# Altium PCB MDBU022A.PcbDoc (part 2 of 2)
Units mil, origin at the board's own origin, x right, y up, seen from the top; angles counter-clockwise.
Board outline 3500 x 2200 mil, 2 copper layers (Top Layer, Bottom Layer), stack 64.8 mil thick; 115 components, 70 nets, 323 pads, 476 vias.
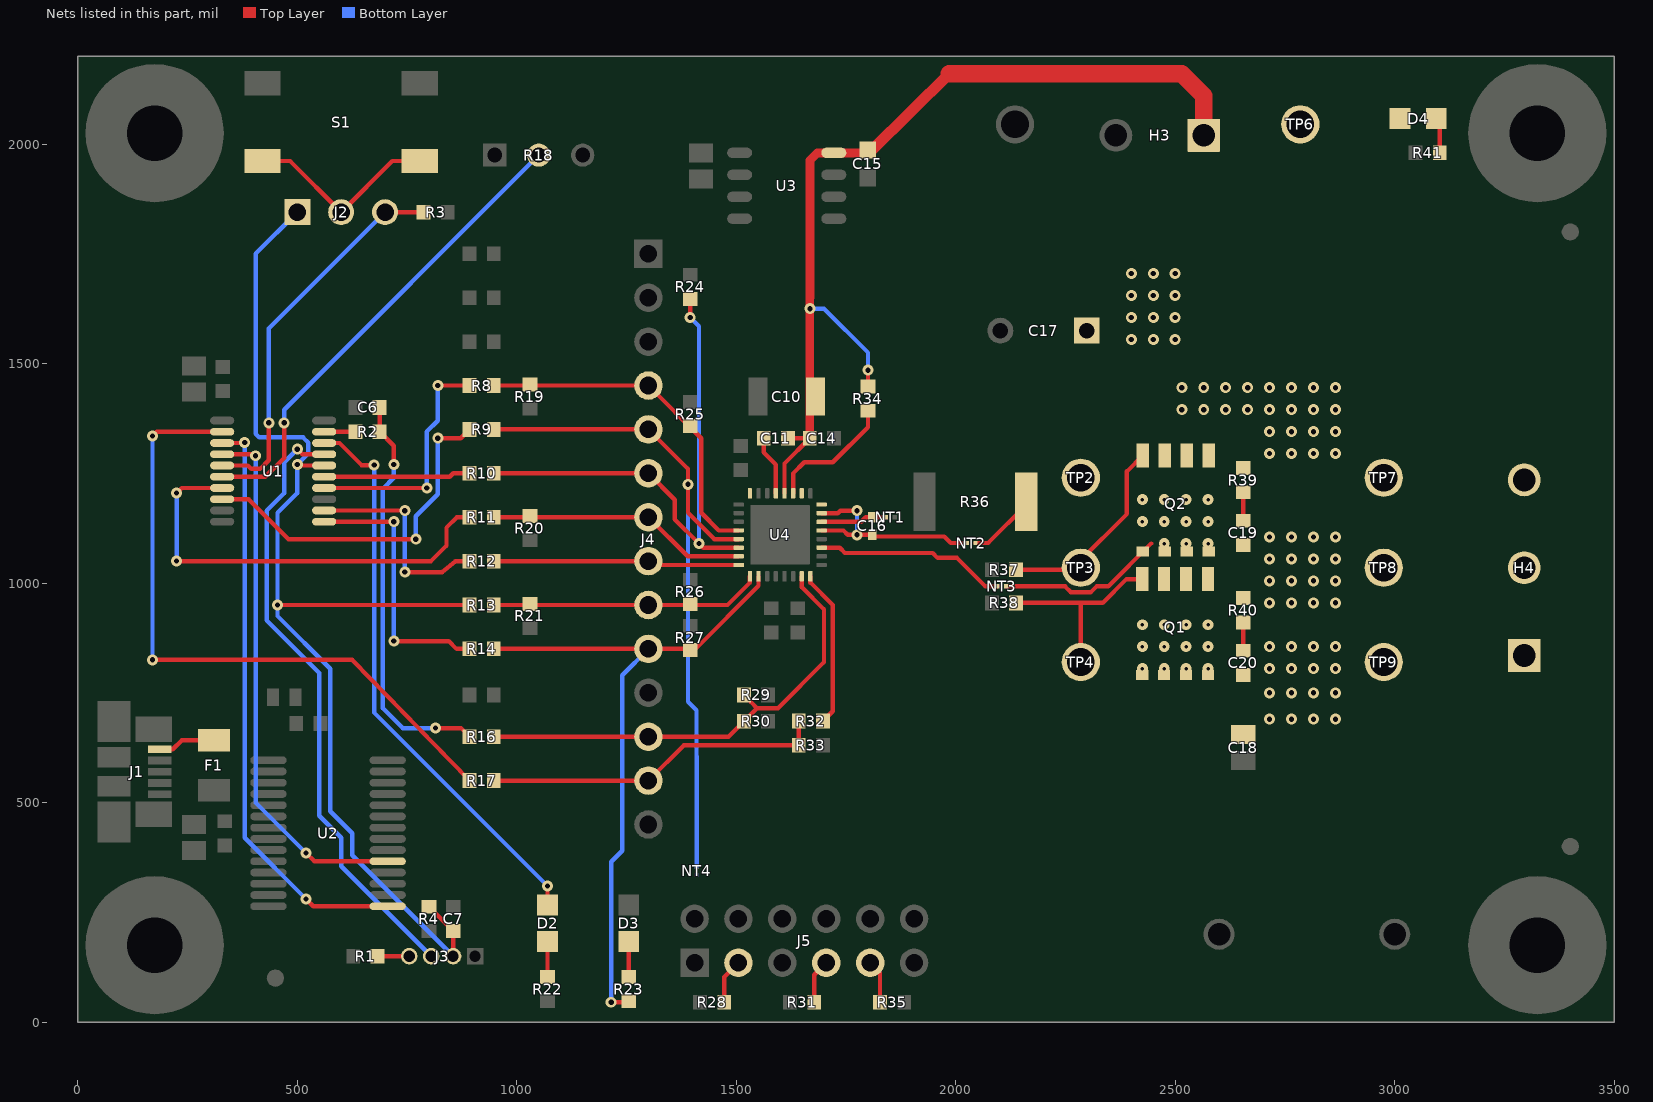
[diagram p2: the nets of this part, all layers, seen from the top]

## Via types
v1: diameter 25, hole 12, Top Layer to Bottom Layer, tented both sides, 446 vias
v2: diameter 25, hole 7.82, Top Layer to Bottom Layer, tented both sides, 23 vias
v3: diameter 19.68, hole 7.87, Top Layer to Bottom Layer, 5 vias
v4: diameter 25, hole 12, Top Layer to Bottom Layer, 2 vias

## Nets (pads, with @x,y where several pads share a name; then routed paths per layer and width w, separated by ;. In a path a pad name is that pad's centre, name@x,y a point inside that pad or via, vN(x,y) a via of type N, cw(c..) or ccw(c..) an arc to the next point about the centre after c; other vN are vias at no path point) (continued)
NetC19_2: C19.2 R39.2 | length 64.9
  Top Layer w10: C19.2@2655,1142.01 R39.2@2655,1206.89
NetC20_2: C20.2 R40.2 | length 64.9
  Top Layer w10: C20.2@2655,845.61 R40.2@2655,910.49
NetD2_2: D2.2 R22.2 | length 81.1
  Top Layer w10: R22.2@1070,102.56 D2.2@1070,183.66
NetD3_2: D3.2 R23.2 | length 81.1
  Top Layer w10: R23.2@1255,102.56 D3.2@1255,183.66
NetD4_2: D4.2 R41.2 | length 76.6
  Top Layer w10: D4.2@3090.75,2054.49 D4.2@3094.53,2058.27 ; R41.2@3103.05,1980 D4.2@3103.05,2051.22
NetF1_2: F1.2 J1.1 | length 138.7
  Top Layer w10: J1.1@180,621.18 216.18,621.18 237.09,642.09 F1.2@310,642.09
NetH4_3: H4.3 NT2.1 Q2.1 Q2.2 Q2.3 R36.2 R39.1 TP2.1 TP7.1 | length 152.3
  Top Layer w10: NT2.1@2045,1091.25 2073.75,1091.25 R36.2@2161.14,1178.64
  other v1: 2715,1295 2765,1295 2815,1295 2865,1295 2715,1345 2765,1345 2815,1345 2865,1345 2515,1395 2565,1395 2615,1395 2665,1395 2715,1395 2765,1395 2815,1395 2865,1395 2515,1445 2565,1445 2615,1445 2665,1445 2715,1445 2765,1445 2815,1445 2865,1445
NetJ2_2: J2.2 S1.1 S1.2 | length 454.7
  Top Layer w10: S1.2@420.87,1961.42 483.58,1961.42 J2.2@600,1845 716.42,1961.42 S1.1@779.13,1961.42
NetJ3_4: J3.4 R1.1 | length 72.4
  Top Layer w10: R1.1@682.56,150 J3.4@755,150
NetJ5_3: J5.3 R28.1 | length 103.4
  Top Layer w10: R28.1@1472.56,45 1472.56,102.56 J5.3@1505,135
NetJ5_7: J5.7 R31.2 | length 101.4
  Top Layer w10: R31.2@1677.56,45 1677.56,107.56 J5.7@1705,135
NetJ5_9: J5.9 R35.2 | length 99.3
  Top Layer w10: J5.9@1805,135 1827.44,112.56 R35.2@1827.44,45
NetQ1_4: Q1.4 R38.2 TP4.1 | length 444.3
  Top Layer w10: R38.2@2137.56,954.7 2260.3,954.7 2334.7,954.7 2389.1,1009.1 Q1.4@2424.65,1009.1 ; TP4.1@2285,820 2285,954.7
NetQ2_4: Q2.4 R37.2 TP3.1 | length 453.3
  Top Layer w10: R37.2@2137.56,1030 2262.55,1030 2282.55,1050 2390,1157.45 2390,1254.35 Q2.4@2426.18,1290.53
NetR2_1: R2.1 U1.19 | length 70.9
  Top Layer w10: U1.19@561.14,1344.57 R2.1@632.01,1344.57
NetR32_1: R32.1 U4.16 | length 360.3
  Top Layer w10: U4.16@1668.9,1015.51 1668.9,1001.1 1720,950 1720,708.11 R32.1@1697.56,685.67
NetU4_24: U4.24
NetU4_26: U4.26
NetU4_32: U4.32
NFAULT: J4.10 R14.1 R23.1 R27.2 U4.10 | length 1565.7
  Top Layer w10: R14.1@947.56,850 J4.10@1300,850 1407,850 1550.79,993.79 U4.10@1550.79,1015.51 ; v1(1215,45) 1252.56,45 R23.1@1255,47.44
  Bottom Layer w10: v1(1215,45) 1215,365 1240,390 1240,790 J4.10@1300,850
NFAULT_MCU: R14.2 U1.11 | length 610.7
  Top Layer w10: U1.11@561.14,1139.84 v1(720,1139.84) ; v1(720,867.82) 845,867.82 862.82,850 R14.2@892.44,850
  Bottom Layer w10: v1(720,867.82) v1(720,1139.84)
NSCS: J4.5 NT4.1 R9.1 U4.5 | length 1597.8
  Top Layer w10: R9.1@948.05,1350 J4.5@1300,1350 1390,1260 v1(1390,1225) 1390,1160 1449.84,1100.16 U4.5@1505.51,1100.16
  Bottom Layer w10: v1(1390,1225) 1390,729.65 1409.5,710.15 1409.5,605.5 1410,605 NT4.1@1410,355
NSCS_MCU: R9.2 U1.8 | length 810.3
  Top Layer w10: U1.8@328.86,1191.02 388.98,1191.02 480,1100 v1(770,1100) ; v1(820,1330) 872.44,1330 R9.2@892.44,1350
  Bottom Layer w10: v1(770,1100) 770,1152.11 820,1202.11 v1(820,1330)
NSLEEP: J4.8 R12.1 U4.8 | length 561.6
  Top Layer w10: R12.1@947.56,1050 J4.8@1300,1050 1308.9,1041.1 U4.8@1505.51,1041.1
NSLEEP_MCU: R12.2 U1.12 | length 480.4
  Top Layer w10: U1.12@561.14,1165.43 v1(745,1165) ; v1(745,1025) 830,1025 860,1050 R12.2@892.44,1050
  Bottom Layer w10: v1(745,1025) v1(745,1165)
OUT1: C19.1 H4.2 NT3.2 Q1.1 Q1.2 Q1.3 Q2.5 Q2.6 Q2.7 Q2.8 R40.1 TP8.1 | length 381.1
  Top Layer w10: NT3.2@2115,992.35 2249.16,992.35 2262.01,979.5 2307.99,979.5 2320.84,992.35 2347.35,992.35 2445,1090
  other v1: 2715,955 2765,955 2815,955 2865,955 2715,1005 2765,1005 2815,1005 2865,1005 2715,1055 2765,1055 2815,1055 2865,1055 2715,1105 2765,1105 2815,1105 2865,1105
  other v2: 2475,1090 2525,1090 2575,1090 2425,1140 2475,1140 2525,1140 2575,1140 2425,1190 2475,1190 2525,1190 2575,1190
POT: R18.2 U1.6 | length 1089.1
  Top Layer w10: U1.6@328.86,1242.2 427.2,1242.2 470,1285 v1(470,1365)
  Bottom Layer w10: v1(470,1365) 470,1395 R18.2@1050,1975
PUSH: J2.3 R3.1 U1.5 | length 879.9
  Top Layer w10: U1.5@328.86,1267.8 387.2,1267.8 395,1260 415,1260 435,1280 v1(435,1365) ; J2.3@700,1845 R3.1@787.44,1845
  Bottom Layer w10: v1(435,1365) 435,1580 J2.3@700,1845
PVDD: C10.1 C11.2 C14.1 C15.1 C17.1 C18.1 C20.1 D4.1 H3.1 H4.1 Q1.5 Q1.6 Q1.7 Q1.8 R34.1 TP6.1 TP9.1 U3.8 U4.28 | length 2159.1
  Top Layer w10: U4.28@1609.84,1204.49 1609.84,1272.4 C14.1@1667.44,1330 C11.2@1617.56,1330 ; C15.1@1797.44,1980 C15.1@1800,1982.56 ; R34.1@1800,1447.56 v1(1800,1485)
  Top Layer w20: C14.1@1667.44,1330 1668.15,1963.15 1685,1980 U3.8@1722.28,1980 C15.1@1797.44,1980
  Top Layer w25: C15.1@1810,1988.05 1985,2160
  Top Layer w40: 1985,2160 2515,2160 2565,2110 H3.1@2565,2020
  Bottom Layer w10: v1(1668.15,1625) 1700,1625 1800,1525 v1(1800,1485)
  other v1: 2715,690 2765,690 2815,690 2865,690 2715,750 2765,750 2815,750 2865,750 2715,805 2765,805 2815,805 2865,805 2715,855 2765,855 2815,855 2865,855 2400,1555 2450,1555 2500,1555 2400,1605 2450,1605 2500,1605 2400,1655 2450,1655 2500,1655 2400,1705 2450,1705 2500,1705
  other v2: 2425,805 2475,805 2525,805 2575,805 2425,855 2475,855 2525,855 2575,855 2425,905 2475,905 2525,905 2575,905
RESET: C7.1 J2.1 J3.2 R4.1 R13.2 U1.16 | length 2671.7
  Top Layer w10: v1(455,950) R13.2@891.95,950 ; v1(500,1270) 502.2,1267.8 U1.16@561.14,1267.8 ; R4.1@800,262.56 800,262.44 C7.1@855,207.44 J3.2@855,150
  Bottom Layer w10: J2.1@500,1845 405,1750 405,1340 413.13,1331.87 513.13,1331.87 525,1320 525,1295 v1(500,1270) 500,1205 455,1160 v1(455,950) 455,925 575,805 575,480 625,430 625,380 J3.2@855,150
RX: U1.4 U2.5 | length 1223.9
  Top Layer w10: U1.4@328.86,1293.39 401.61,1293.39 v1(405,1290) ; v1(520,385) 538.98,366.02 U2.5@705.83,366.02
  Bottom Layer w10: v1(405,1290) 405,500 v1(520,385)
S_N: C16.2 NT1.1 U4.22 | length 150.2
  Top Layer w10: U4.22@1694.49,1139.53 1784.84,1139.53 1795,1149.69 C16.2@1810,1149.69 ; C16.2@1810.31,1150 NT1.1@1840.76,1150
S_P: C16.1 NT2.2 U4.21 U4.23 | length 492.6
  Top Layer w10: U4.21@1694.49,1119.84 1744.2,1119.84 1754.04,1110 v4(1775,1110) ; U4.23@1694.49,1159.21 1731.48,1159.21 1737.26,1165 v4(1775,1165) ; v4@1765.32,1110.32 C16.1@1810,1110.32 1810,1106.07 1973.93,1106.07 1988.75,1091.25 NT2.2@2025,1091.25
  Bottom Layer w10: v4(1775,1110) v4(1775,1165)
SCLK: J4.7 R11.1 R20.2 U4.7 | length 594.9
  Top Layer w10: R11.1@947.56,1150 J4.7@1300,1150 1389.21,1060.79 U4.7@1505.51,1060.79
SCLK_MCU: R11.2 U1.7 | length 996.6
  Top Layer w10: v1(225,1050) 804.65,1050 840,1085.35 840,1126.4 863.6,1150 R11.2@892.44,1150 ; v1(225,1205) 236.61,1216.61 U1.7@328.86,1216.61
  Bottom Layer w10: v1(225,1050) v1(225,1205)
SDI: J4.6 R10.1 R24.2 U4.6 | length 1215.3
  Top Layer w10: R10.1@947.56,1250 J4.6@1300,1250 1360,1190 1360,1145 v1(1415,1090) 1424.53,1080.47 U4.6@1505.51,1080.47 ; v1(1395,1605) R24.2@1395,1642.44
  Bottom Layer w10: v1(1395,1605) 1415,1585 v1(1415,1090)
SDI_MCU: R10.2 U1.15 | length 334
  Top Layer w10: U1.15@561.14,1242.2 847.2,1242.2 855,1250 R10.2@891.95,1250
SDO: J4.4 R8.1 R19.2 R25.1 U4.4 | length 794.3
  Top Layer w10: R8.1@947.56,1450 J4.4@1300,1450 1420,1330 1420,1160 1460.16,1119.84 U4.4@1505.51,1119.84
SDO_MCU: R8.2 U1.14 | length 549.5
  Top Layer w10: U1.14@561.14,1216.61 v1(795,1216.61) ; v1(820,1450) R8.2@891.95,1450
  Bottom Layer w10: v1(795,1216.61) 795,1345 820,1370 v1(820,1450)
SH: NT3.1 U4.19 | length 437
  Top Layer w10: U4.19@1694.49,1080.47 1735.49,1080.47 1747.46,1068.5 1947.46,1068.5 1958.71,1057.25 2002.75,1057.25 2067.65,992.35 NT3.1@2095,992.35
SO: J4.13 R17.1 R32.2 R33.2 | length 783.3
  Top Layer w10: R17.1@947.56,550 J4.13@1300,550 1380.67,630.67 R33.2@1642.44,630.67 ; R33.2@1642.44,633.46 R32.2@1642.44,688.46
SO_MCU: R17.2 U1.2 | length 1511.4
  Top Layer w10: v1(170,825) 625,825 R17.2@892.44,550 ; v1(170,1335) 179.57,1344.57 U1.2@328.86,1344.57
  Bottom Layer w10: v1(170,825) v1(170,1335)
STATUS: D2.1 U1.18 | length 1300.7
  Top Layer w10: U1.18@561.14,1318.98 596.02,1318.98 645,1270 646.27,1268.73 v1(675,1268.73) ; D2.1@1070,266.34 v1(1070,310)
  Bottom Layer w10: v1(675,1268.73) 675,1235 675,705 v1(1070,310)
TEST: J3.3 U1.17 | length 1405.3
  Top Layer w10: v1(500,1305) 511.61,1293.39 U1.17@561.14,1293.39
  Bottom Layer w10: v1(500,1305) 470,1275 470,1205 430,1165 430,915 550,795 550,470 600,420 600,355 J3.3@805,150
TX: U1.3 U2.1 | length 1342.1
  Top Layer w10: U1.3@328.86,1318.98 378.98,1318.98 v1(380,1320) ; v1(520,280) 536.34,263.66 U2.1@705.83,263.66
  Bottom Layer w10: v1(380,1320) 380,420 v1(520,280)
VCP: C11.1 U4.29 | length 137
  Top Layer w10: C11.1@1562.44,1330 1562.44,1297.56 1590.16,1269.84 U4.29@1590.16,1204.49
VDRAIN: R34.2 U4.27 | length 296.1
  Top Layer w10: U4.27@1629.53,1204.49 1629.53,1249.53 1655,1275 1720,1275 1800,1355 R34.2@1800,1391.95
VREF: J4.12 R16.1 R29.2 R30.1 U4.15 | length 1081.8
  Top Layer w10: R16.1@947.56,650 J4.12@1300,650 1482.44,650 R30.1@1517.44,685 1547.44,715 ; R29.2@1517.44,745 1532.44,730 1547.44,715 ; U4.15@1649.21,1015.51 1649.21,990.79 1700,940 1700,820 1595,715 1547.44,715
VREF_MCU: C6.1 R2.2 R16.2 | length 933.1
  Top Layer w10: C6.1@687.56,1400 R2.2@687.56,1345 719.89,1312.67 v1(719.89,1270) ; v1(815,669.61) 872.83,669.61 R16.2@892.44,650
  Bottom Layer w10: v1(719.89,1270) 719.89,1239.89 695,1215 695,715 740.39,669.61 v1(815,669.61)
WDFLT: J4.9 R13.1 R21.2 R26.2 U4.9 | length 619.1
  Top Layer w10: R13.1@947.56,950 J4.9@1300,950 1480,950 1531.1,1001.1 U4.9@1531.1,1015.51
pads on no net: FID1.1 FID2.1 FID3.1 H9.0 J1.4 J5.5 SH-J1.0 SH-J2.0 U2.2 U2.3 U2.6 U2.8 U2.9 U2.10 U2.11 U2.12 U2.13 U2.14 U2.19 U2.22 U2.23 U2.24 U2.27 U2.28 U3.4 U3.5 U4.

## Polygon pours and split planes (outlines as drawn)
PVDD on Top Layer "PVDD" (solid, remove dead copper, pour order 50): 3035.14,1515 2180,1515 2180,1771.71 2492.75,1771.71 2492.75,2180 3035.14,2180 3035.14,1889.38
NetH4_3 on Top Layer "SL" (solid, remove dead copper, pour order 47): 3364.5,1170 2690.12,1170 2690.12,1219.88 2400.78,1219.88 2400.78,1065 2094.5,1065 2094.5,1515 2745,1515 2859.27,1590 3364.5,1590
OUT1 on Top Layer "OUT" (solid, remove dead copper, pour order 49): 2340,1225 2340,900 3365,900 3365,1160 2615,1155 2615,1225
GND on Top Layer "GND_PLANE" (solid, remove dead copper, pour order 52): 1.28,2199.84 3501.28,2199.84 3501.28,-0.16 1.28,-0.16
PVDD on Top Layer "PVDD" (solid, remove dead copper, pour order 45): 3365,631.07 2215,631.07 2215,748.57 2245,748.57 2330,950 2615,950 2615,815 2683.08,815 2683.08,892.74 3365,892.74
GND on Bottom Layer "GND_PLANE" (solid, remove dead copper, pour order 53): -0.46,2191.22 3499.54,2191.22 3499.54,-8.78 -0.46,-8.78
PVDD on Bottom Layer "PVDD" (solid, remove dead copper, pour order 51): 2840,1897.6 2390,1400 2390,950 2602.63,950 2700,880 3360,880 3360,665 2780,665 2715,625 2245,625 2110,739.5 2110,1185 2150,1455 2150,1645 2435,1930 2435,2180 2840,2180
NetH4_3 on Bottom Layer "SL" (solid, remove dead copper, pour order 48): 3361.29,1185 2881.13,1175 2750,1250 2406.59,1250 2406.59,1515 2750,1515 2859.27,1590 3361.29,1590
OUT1 on Bottom Layer "OUT" (solid, remove dead copper, pour order 46): 2400.78,1235 2400.78,965 2610,965 2705,890 3360.78,890 3360.78,1170 2870,1170 2750,1235

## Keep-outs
Keep-Out Layer:
  the board outline again, w10
  text ".Layer_Name" at 577,-858.49 h60

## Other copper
Top Layer:
  text ".Layer_Name" at 577,-858.49 h60
Bottom Layer:
  text ".Layer_Name" at 577,-858.49 h60

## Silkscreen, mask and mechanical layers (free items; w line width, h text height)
Top Overlay:
  circle w10: c1445,1210 r5
  circle w10: c280,1390 r5
  circle w10: c1457.56,2016.18 r5
  circle w10: c940,150 r5
  lines w7: 2015,395 2515,395 ; 2090,465 2515,465
  lines w10: 1950,1105 1950,720 2030,640 2615,640 ; 1950,1265 1950,1500 1990,1540 ; 2090,165 2090,535 ; 2195,1845 2235,1845 ; 2310,167 2310,460 ; 2410,1610 2675,1610 2790,1495 2790,720 2710,640 2695,640 ; 3230,695 3230,735 ; 1375,305 1375,545 1920,545 1920,305 1375,305 ; 1465,850 1750,850 1750,1535 1465,1535 1465,850 ; 2015,165 2015,535 2515,535 2515,165 2015,165
  text "GND" at 2065,1910 h70
  text "PVDD" at 2705,1910 h70
  text "POT" at 990,1815 h70
  text "+" at 2710,1815 h60
  text "Vin" at 2585,1750 h60
  text "3.3V" at 1135,1735 h55
  text "RST" at 435,1730 h70
  text "PUSH" at 635,1730 h70
  text "IN1" at 1165,1635 h55
  text "DRV870XD-Q1" at 1390,1550 h70
  text "IN2" at 1165,1535 h55
  text "PIN4" at 1130,1435 h55
  text "PIN5" at 1130,1335 h55
  text "PIN6" at 1130,1235 h55
  text "SL" at 2895,1205 h70 r90
  text "PIN7" at 1130,1135 h55
  text "SL" at 2245,1115 h70
  text "nSLEEP" at 1050,1035 h55
  text "OUT" at 2895,970 h70 r90
  text "PIN9" at 1130,935 h55
  text "GL" at 2245,905 h70
  text "nFAULT" at 1050,835 h55
  text "PVDD" at 2915,740 h70 r90
  text "MODE" at 1095,735 h55
  text "Hot  / Surface" at 1960,715 h70
  text "GH" at 2245,695 h70
  text "VREF" at 1105,635 h55
  text "SRC/SNK (mA)" at 1610,565 h50
  text "IDRIVE" at 1385,560 h70
  text "SO" at 1168,535 h55
  text "260/440" at 1395,525 h65 r270
  text "210/350" at 1485,525 h65 r270
  text "155/265" at 1585,525 h65 r270
  text "P" at 2040,491 h30
  text "DRV870XD-Q1" at 2160,485 h28
  text "20/40" at 1785,465 h65 r270
  text "'.PRJ_Number' .PCB_Rev" at 2740,465 h70
  text "50/95" at 1690,460 h65 r270
  text "10/20" at 1865,460 h65 r270
  text "I" at 2040,449 h30
  text "GND" at 1140,435 h50
  text "2" at 2195,415 h28
  text "3" at 2405,415 h28
  text "N" at 2040,407 h30
  text "4" at 2040,345 h28
  text "GND" at 2125,345 h28
  text "SDO" at 2345,345 h28
  text "STATUS" at 980,315 h70 r270
  text "nFAULT" at 1165,315 h70 r270
  text "5" at 2040,305 h28
  text "IDRIVE" at 2125,305 h28
  text "nSCS" at 2345,305 h28
  text "6" at 2040,265 h28
  text "VDS" at 2125,265 h28
  text "SDI" at 2345,265 h28
  text "7" at 2040,225 h28
  text "GND" at 2125,225 h28
  text "SCLK" at 2345,225 h28
  text "9" at 2040,185 h28
  text "GND" at 2125,185 h28
  text "WDFLT" at 2350,185 h28
  text "GND" at 2740,179.33 h70
  text ".Layer_Name" at 577,-858.49 h60
Bottom Overlay:
  text ".Layer_Name" at 577,-858.49 h60
Top Paste:
  text ".Layer_Name" at 577,-858.49 h60
Bottom Paste:
  text ".Layer_Name" at 577,-858.49 h60
Top Solder:
  text ".Layer_Name" at 577,-858.49 h60
  text ".Layer_Name" at 577,-858.49 h60
Bottom Solder:
  text ".Layer_Name" at 577,-858.49 h60
Drill Guide:
  text ".Layer_Name" at 577,-858.49 h60
M1 Board Outline:
  the board outline again, w10
  text ".Layer_Name" at 577,-858.49 h60
M2 Board Dimensions:
  rectangle: 125,-400 500,-275
  rectangle: 0,-275 125,-150
  lines w7: 0,-275 1000,-275 ; 125,-400 125,-150 ; 250,-400 250,-150 ; 500,-400 500,-150 ; 750,-400 750,-150 ; 0,-400 0,-150 1000,-150 1000,-400 0,-400
  text ".Layer_Name" at 577,-858.49 h60
M3 3D STEP Top:
  text ".Layer_Name" at 577,-858.49 h60
M4 3D STEP Bottom:
  text ".Layer_Name" at 577,-858.49 h60
M5 Assembly Top:
  lines w10: -292,-930.17 6308,-930.17 ; -292,-726.83 6310,-726.83 ; -292,-523.5 -292,-1133.5 3713,-1133.5 6310,-1133.5 6310,-523.5 -291.5,-523.5 -291.5,-1133.5 1284,-1133.5 ; 2173,-1133.5 2173,-523.5 ; 3440,-726.83 3440,-523.5 ; 4280,-726.83 4280,-523.5 ; 4902,-1140 4902,-937.17
  text "COMPONENTS MARKED 'DNP' SHOULD NOT BE POPULATED." at 1153.5,-318.5 h60
  text "ASSEMBLY VARIANT:" at 1153,-434 h60
  text ".VariantName" at 2189,-434 h60
  text "PCB VIEWED FROM TOP SIDE" at -228.5,-655.67 h60
  text "BOARD #:" at 2248,-655.67 h60
  text ".PRJ_Number" at 2793.5,-655.67 h60
  text "REV:" at 3638,-655.67 h60
  text ".PCB_Rev" at 3929.5,-655.67 h60
  text "SVN REV:" at 4476,-655.67 h60
  text ".VersionControl_RevNumber" at 4982,-655.67 h60
  text "TID #:" at 2248,-859 h60
  text ".TID" at 2793.5,-859 h60
  text "PLOT NAME =" at -228.5,-1064.34 h60
  text ".plot_File_Name" at 577,-1064.34 h60
  text "GENERATED    :" at 2250,-1064.34 h60
  text ".Print_Date" at 3119.5,-1064.34 h60
  text ".Print_Time" at 3848.5,-1064.34 h60
  text "TEXAS INSTRUMENTS" at 5113,-1064.34 h60
M6 Assembly Bottom:
  lines w10: -292.5,-727.33 6309.5,-727.33 ; -290.5,-930.67 6309.5,-930.67 ; 1115.5,-1140.5 1115.5,-937.67 ; 1737.5,-727.33 1737.5,-524 ; 2577.5,-727.33 2577.5,-524 ; 3844.5,-1134 3844.5,-524 ; 4733.5,-1134 6309,-1134 6309,-524 -292.5,-524 -292.5,-1134 2304.5,-1134 6309.5,-1134 6309.5,-524
  text "COMPONENTS MARKED 'DNP' SHOULD NOT BE POPULATED." at 6102,-318 h60
  text ".VariantName" at 5058,-434 h60
  text "ASSEMBLY VARIANT:" at 6097,-434 h60
  text ".VersionControl_RevNumber" at 1035.5,-656.17 h60
  text "SVN REV:" at 1541.5,-656.17 h60
  text ".PCB_Rev" at 2088,-656.17 h60
  text "REV:" at 2379.5,-656.17 h60
  text ".PRJ_Number" at 3224,-656.17 h60
  text "BOARD #:" at 3769.5,-656.17 h60
  text "PCB VIEWED FROM BOTTOM SIDE" at 6246,-656.17 h60
  text ".TID" at 3224,-859.5 h60
  text "TID #:" at 3769.5,-859.5 h60
  text "TEXAS INSTRUMENTS" at 904.5,-1064.84 h60
  text ".Print_Time" at 2169,-1064.84 h60
  text ".Print_Date" at 2898,-1064.84 h60
  text "GENERATED    :" at 3767.5,-1064.84 h60
  text ".plot_File_Name" at 5440.5,-1064.84 h60
  text "PLOT NAME =" at 6246,-1064.84 h60
M9 Title Sheet:
  drawing of 57 lines, arcs and shapes, not listed
  text "1" at 739.84,8036.5 h70
  text "2" at 3235.5,8036.5 h70
  text "3" at 5724.84,8036.5 h70
  text "4" at 8231.51,8036.5 h70
  text "5" at 10730.5,8036.5 h70
  text "6" at 13235.5,8036.5 h70
  text "A" at -416.5,6893.5 h70
  text "A" at 14383.5,6893.5 h70
  text "B" at -416.5,4513.5 h70
  text "B" at 14383.5,4513.5 h70
  text "C" at -416.5,2138.5 h70
  text "C" at 14383.5,2138.5 h70
  text "PROJECT TITLE:" at 11343.5,277.5 h45
  text ".PRJ_Title" at 11393.5,144.17 h70
  text "DESIGNED FOR:" at 11343.5,-23.5 h45
  text ".PRJ_Customer" at 11393.5,-163.5 h70
  text "D" at -416.5,-231.5 h70
  text "D" at 14383.5,-231.5 h70
  text "FILE NAME:" at 11343.5,-323.5 h45
  text ".PCB_File_Name_No_Path" at 11393.5,-443.5 h70
  text "Texas Instruments (TI) and/or its licensors do not warrant the accuracy or completeness of this specification" at 6374,-605.34 h45
  text "ENGINEER:" at 11343.5,-613.5 h45
  text "LAYOUT BY:" at 12848.5,-613.5 h45
  text "or any information contained therein. TI and/or its licensors do not warrant that this design will meet" at 6329.01,-718 h45
  text ".PRJ_Engineer" at 11393.5,-768.49 h70
  text ".PCB_Layout" at 12899,-768.49 h70
  text "the specifications, will be suitable for your application or fit for any particular purpose, or will operate in" at 6329.01,-830.67 h45
  text ".Layer_Name" at 577,-858.49 h60
  text "ALTIUM DESIGNER VERSION:" at 12848.5,-923.5 h45
  text "an implementation. TI and/or its licensors do not warrant that the design is production worthy. You should" at 6329.01,-943.33 h45
  text "completely validate and test your design implementation to confirm the system functionality for your application." at 6374,-1056 h45
  text ".print_Scale" at 11393.5,-1056.83 h70
  text ".Application_BuildNumber" at 12899,-1056.83 h70
  text "1" at 739.84,-1263.5 h70
  text "2" at 3235.5,-1263.5 h70
  text "3" at 5724.84,-1263.5 h70
  text "4" at 8231.51,-1263.5 h70
  text "5" at 10730.5,-1263.5 h70
  text "6" at 13235.5,-1263.5 h70
M10 Fab Notes:
  drawing of 173 lines, arcs and shapes, not listed
  text "DESIGN INFORMATION" at 12377.02,6201 h60
  text "MIN. TRACK WIDTH:" at 11732.46,6021 h60
  text "8" at 12828.7,6021 h60
  text "MIL" at 12983.46,6021 h60
  text "MIN. CLEARANCE:" at 11732.46,5889 h60
  text "0.2" at 12768.7,5889 h60
  text "mm" at 12983.46,5889 h60
  text "MIN. VIA PAD SIZE:" at 11732.46,5757 h60
  text "24" at 12798.71,5757 h60
  text "MIL" at 12983.46,5757 h60
  text "0.05mm (2MIL)" at 12427.46,5615.29 h60
  text "MINIMUM ANNULAR RING" at 11403.23,5611 h60
  text "EXTERNAL" at 13135.46,5611 h60
  text "PER" at 11603.23,5493 h60
  text "IPC-D-275 CLASS 2 LEVEL C" at 11823.23,5493 h60
  text "MIL, HOLES" at 13311.46,5380.71 h60
  text "+/-" at 12919,5380 h60
  text "+/-" at 13773,5380 h60
  text "REGISTRATION TOLERANCES:" at 11403.23,5375 h60
  text "METAL" at 12603,5375 h60
  text "5" at 13179.2,5375 h60
  text "3" at 14012.2,5375 h60
  text "MIL" at 14128.46,5375 h60
  text "+/-" at 13773,5262 h60
  text "HOLE SIZE TOLERANCE (UNLESS OTHERWISE SPECIFIED):" at 11403.23,5257 h60
  text "3" at 14012.2,5257 h60
  text "MIL" at 14128.46,5257 h60
  text "MATERIAL:" at 11328.46,5047.54 h60
  text "FR-4 High Tg" at 12314.9,4907.21 h60
  text "FR-408" at 11749.46,4898.64 h60
  text "OTHER" at 13237.46,4898.64 h60
  text "X" at 12160,4895 h60
  text "62 MIL (1.6mm) +/-10%" at 12069.56,4735.92 h60
  text "THICKNESS:" at 11403.23,4731.64 h60
  text "X" at 11941.4,4731.64 h60
  text "OTHER" at 13354.46,4731.64 h60
  text "TOLERANCE:" at 11403.23,4573.64 h60
  text "X" at 12242.53,4573.64 h60
  text "ANSI IPC-6012 TYPE 3 CLASS 2" at 12429.48,4573.64 h60
  text "OTHER +/-" at 12429.46,4417.64 h60
  text "BOW & TWIST:" at 11403.23,4260.64 h60
  text "X" at 12242.53,4260.64 h60
  text "ANSI IPC-6012 TYPE 3 CLASS 2" at 12429.48,4260.64 h60
  text "OTHER +/-" at 12429.46,4102.13 h60
  text "DRILLING:" at 11328.46,3963.64 h60
  text "REFERENCE:" at 11403.23,3846.64 h60
  text "X" at 12051.46,3846.64 h60
  text "AS SHOWN" at 12238.46,3846.64 h60
  text "X" at 12952.46,3846.64 h60
  text "NC_DRILL FILES" at 13089.46,3846.64 h60
  text "PTH MIN COPPER THICKNESS:" at 11403.23,3688.64 h60
  text "X" at 12753.46,3688.64 h60
  text "1MIL" at 12890.46,3688.64 h60
  text "OTHER" at 13387.46,3688.64 h60
  text "BOARD FINISH:" at 11328.46,3529.64 h60
  text "SILKSCREEN:" at 11483.68,3411.64 h60
  text "X" at 12432.46,3411.64 h60
  text "TOP" at 12558.46,3411.64 h60
  text "BOTTOM" at 13069.46,3411.64 h60
  text "SILKSCREEN COLOR:" at 11483.68,3244.64 h60
  text "X" at 12431.42,3244.64 h60
  text "WHITE" at 12558.46,3244.64 h60
  text "OTHER" at 13069.46,3244.64 h60
  text "X" at 12562.42,3085.44 h60
  text "GREEN" at 12689.46,3085.44 h60
  text "OTHER" at 13307.46,3085.44 h60
  text "SOLDER RESIST COLOR:" at 11483.68,3074.64 h60
  text "X" at 12562.42,2915.44 h60
  text "MATTE" at 12689.46,2915.44 h60
  text "SEMI-GLOSS" at 13307,2914.8 h60
  text "IMMERSION GOLD (ENIG)" at 12389.46,2726.92 h60
  text "ENEPIG" at 13727,2723.64 h60
  text "SURFACE FINISH:" at 11328.46,2722.64 h60
  text "X" at 12202.51,2722.64 h60
  text "IMM. TIN/SILVER OR EQUIV" at 11658,2565.64 h60
  text "OTHER" at 13089.46,2565.64 h60
  text "ARRAY/PANEL:" at 11328.46,2386.64 h60
  text "CUT AND TRIM PER M1 BOARD OUTLINE" at 12389.46,2382.35 h60
  text "N.C. ROUTE" at 12389.46,2230.64 h60
  text "X" at 13068.46,2230.64 h60
  text "V. SCORE" at 13255.46,2230.64 h60
  text "CERTIFICATION:" at 11328.46,2093.64 h60
  text "MATERIALS AND WORKMANSHIP FOR ALL PCBS" at 12053.46,2093.64 h60
  text "TO MEET OR EXCEED THE REQUIREMENTS OF:" at 12053.46,1995.64 h60
  text "X" at 11679.96,1859.13 h60
  text "ANSI IPC-A-600F CLASS ->" at 11818.96,1859.13 h60
  text "X" at 13458.02,1859.13 h60
  text "2" at 13576.96,1859.14 h60
  text "1" at 13261.96,1857.64 h60
  text "3" at 13930.96,1857.64 h60
  text "X" at 12494.02,1699.64 h60
  text "RoHS" at 12630.96,1699.64 h60
  text "OTHER" at 13275.36,1699.64 h60
  text "PER ORDER" at 13672.42,1699.64 h60
  text "ALL BOARDS MUST MEET OR EXCEED UL94-V0 REQUIREMENTS." at 11356,1534 h60
  text "PCB MUST BEAR THE UL94V-0 UL REGISTERED MATERIAL ID NUMBER" at 11356,1414 h60
  text "ADDITIONAL REQUIREMENTS:" at 11328.46,1240.64 h60
  text "MICROSECTION:" at 11403.23,1125.64 h60
  text "YES" at 12308.96,1125.64 h60
  text "REQUIRED" at 13170.46,969.49 h60
  text "BARE BOARD ELEC. TEST:" at 11403.23,966.64 h60
  text "NONE" at 12708.96,966.64 h60
  text "X" at 13043.46,966.64 h60
  text "PER ORDER" at 13762.46,966.64 h60
  text ".Layer_Name" at 577,-858.49 h60
M11 Gerber Information:
  lines w10: -292,-930.17 6308,-930.17 ; -292,-726.83 6310,-726.83 ; -292,-523.5 -292,-1133.5 3713,-1133.5 6310,-1133.5 6310,-523.5 -291.5,-523.5 -291.5,-1133.5 1284,-1133.5 ; 2173,-1133.5 2173,-523.5 ; 3440,-726.83 3440,-523.5 ; 4280,-726.83 4280,-523.5 ; 4902,-1140 4902,-937.17
  text "ALL ARTWORK VIEWED FROM TOP SIDE" at -228.5,-655.67 h60
  text "BOARD #:" at 2248,-655.67 h60
  text ".PRJ_Number" at 2793.5,-655.67 h60
  text "REV:" at 3638,-655.67 h60
  text ".PCB_Rev" at 3929.5,-655.67 h60
  text "SVN REV:" at 4476,-655.67 h60
  text ".VersionControl_RevNumber" at 4982,-655.67 h60
  text "LAYER NAME =" at -228.5,-858.49 h60
  text "TID #:" at 2248,-859 h60
  text ".TID" at 2793.5,-859 h60
  text "PLOT NAME =" at -228.5,-1064.34 h60
  text ".plot_File_Name" at 577,-1064.34 h60
  text "GENERATED    :" at 2250,-1064.34 h60
  text ".Print_Date" at 3119.5,-1064.34 h60
  text ".Print_Time" at 3848.5,-1064.34 h60
  text "TEXAS INSTRUMENTS" at 5113,-1064.34 h60
M12 Stackup:
  drawing of 165 lines, arcs and shapes, not listed
  text "Layer" at 9797.84,7830 h60
  text "Name" at 10207.76,7830 h60
  text "Material" at 11067.52,7830 h60
  text "Thickness" at 11927.29,7830 h60
  text "Constant" at 12577.12,7830 h60
  text "Board Layer Stack" at 13146.99,7830 h60
  text "1" at 9797.84,7710 h60
  text "Top Overlay" at 10207.76,7710 h60
  text "2" at 9797.84,7590 h60
  text "Top Solder" at 10207.76,7590 h60
  text "Solder Resist" at 11067.52,7590 h60
  text "0.40mil" at 11927.29,7590 h60
  text "3.5" at 12577.12,7590 h60
  text "3" at 9797.84,7470 h60
  text "Top Layer" at 10207.76,7470 h60
  text "Copper" at 11067.52,7470 h60
  text "2.80mil" at 11927.29,7470 h60
  text "4" at 9797.84,7350 h60
  text "Dielectric1" at 10207.76,7350 h60
  text "FR-4" at 11067.52,7350 h60
  text "59.20mil" at 11927.29,7350 h60
  text "4.8" at 12577.12,7350 h60
  text "5" at 9797.84,7230 h60
  text "Bottom Layer" at 10207.76,7230 h60
  text "Copper" at 11067.52,7230 h60
  text "2.80mil" at 11927.29,7230 h60
  text "6" at 9797.84,7110 h60
  text "Bottom Solder" at 10207.76,7110 h60
  text "Solder Resist" at 11067.52,7110 h60
  text "0.40mil" at 11927.29,7110 h60
  text "3.5" at 12577.12,7110 h60
  text ".Layer_Name" at 577,-858.49 h60
M13 Component Bodies Top:
  text ".Layer_Name" at 577,-858.49 h60
M14 Component Bodies Bottom:
  text ".Layer_Name" at 577,-858.49 h60
M15 Courtyards Top:
  text ".Layer_Name" at 577,-858.49 h60
M16 Courtyards Bottom:
  text ".Layer_Name" at 577,-858.49 h60
Drill Drawing:
  lines w10: 4046.76,834.42 4068.9,845.49 4091.04,834.42 4079.97,856.56 4091.04,878.69 4068.9,867.63 4046.76,878.69 4057.83,856.56 4046.76,834.42 ; 4046.76,978.32 4091.04,978.32 4068.9,934.04 4046.76,978.32 ; 4046.76,1033.66 4091.04,1033.66 4091.04,1077.94 4046.76,1077.94 4046.76,1033.66 ; 4046.76,1144.35 4057.83,1144.35 4068.9,1133.29 4079.97,1144.35 4091.04,1144.35 4079.97,1155.42 4091.04,1166.49 4079.97,1166.49 4068.9,1177.56 4057.83,1166.49 4046.76,1166.49 4057.83,1155.42 4046.76,1144.35 ; 4046.76,1277.18 4091.04,1277.18 4068.9,1232.91 4046.76,1277.18 ; 4046.76,1432.15 4046.76,1443.22 4057.83,1454.29 4046.76,1465.36 4046.76,1476.43 4057.83,1476.43 4068.9,1465.36 4079.97,1476.43 4091.04,1476.43 4091.04,1465.36 4079.97,1454.29 4091.04,1443.22 4091.04,1432.15 4079.97,1432.15 4068.9,1443.22 4057.83,1432.15 4046.76,1432.15 ; 4046.76,1542.84 4057.83,1542.84 4057.83,1531.77 4079.97,1531.77 4079.97,1542.84 4091.04,1542.84 4091.04,1564.98 4079.97,1564.98 4079.97,1576.05 4057.83,1576.05 4057.83,1564.98 4046.76,1564.98 4046.76,1542.84 ; 4046.76,1841.71 4057.83,1841.71 4068.9,1830.64 4079.97,1841.71 4091.04,1841.71 4079.97,1852.78 4091.04,1863.85 4079.97,1863.85 4068.9,1874.92 4057.83,1863.85 4046.76,1863.85 4057.83,1852.78 4046.76,1841.71 ; 4055.62,843.27 4068.9,849.91 4082.18,843.27 4075.54,856.56 4082.18,869.84 4068.9,863.2 4055.62,869.84 4062.26,856.56 4055.62,843.27 ; 4055.62,969.46 4082.18,969.46 4068.9,942.9 4055.62,969.46 ; 4055.62,1148.78 4062.26,1148.78 4068.9,1142.14 4075.54,1148.78 4082.18,1148.78 4075.54,1155.42 4082.18,1162.06 4075.54,1162.06 4068.9,1168.71 4062.26,1162.06 4055.62,1162.06 4062.26,1155.42 4055.62,1148.78 ; 4055.62,1441.01 4055.62,1447.65 4062.26,1454.29 4055.62,1460.93 4055.62,1467.57 4062.26,1467.57 4068.9,1460.93 4075.54,1467.57 4082.18,1467.57 4082.18,1460.93 4075.54,1454.29 4082.18,1447.65 4082.18,1441.01 4075.54,1441.01 4068.9,1447.65 4062.26,1441.01 4055.62,1441.01 ; 4055.62,1547.27 4062.26,1547.27 4062.26,1540.63 4075.54,1540.63 4075.54,1547.27 4082.18,1547.27 4082.18,1560.55 4075.54,1560.55 4075.54,1567.2 4062.26,1567.2 4062.26,1560.55 4055.62,1560.55 4055.62,1547.27
  lines w12: 4006,804.53 5895.11,804.53 ; 4006,1900.38 5895.11,1900.38 ; 4321.63,704.91 4321.63,2000 ; 4638.82,704.91 4638.82,2000 ; 5260.56,704.91 5260.56,2000 ; 5504.88,704.91 5504.88,2000 ; 4006,704.91 5895.11,704.91 5895.11,2000 4006,2000 4006,704.91
  text "Symbol" at 4065.77,1930.26 h72
  text "Quantity" at 4351.52,1930.26 h72
  text "Finished Hole Size" at 4668.7,1930.26 h72
  text "Plated" at 5290.45,1930.26 h72
  text "Hole Type" at 5534.77,1930.26 h72
  text "23" at 4351.52,1830.64 h60
  text "7.82mil (0.199mm)" at 4668.7,1830.64 h60
  text "PTH" at 5290.45,1830.64 h60
  text "Round" at 5534.77,1830.64 h60
  text "5" at 4351.52,1731.02 h60
  text "7.87mil (0.200mm)" at 4668.7,1731.02 h60
  text "PTH" at 5290.45,1731.02 h60
  text "Round" at 5534.77,1731.02 h60
  text "C" at 4044.14,1721.03 h44.28
  text "448" at 4351.52,1631.4 h60
  text "12.00mil (0.305mm)" at 4668.7,1631.4 h60
  text "PTH" at 5290.45,1631.4 h60
  text "Round" at 5534.77,1631.4 h60
  text "D" at 4044.14,1621.4 h44.28
  text "4" at 4351.52,1531.77 h60
  text "25.59mil (0.650mm)" at 4668.7,1531.77 h60
  text "PTH" at 5290.45,1531.77 h60
  text "Round" at 5534.77,1531.77 h60
  text "3" at 4351.52,1432.15 h60
  text "33.46mil (0.850mm)" at 4668.7,1432.15 h60
  text "PTH" at 5290.45,1432.15 h60
  text "Round" at 5534.77,1432.15 h60
  text "2" at 4351.52,1332.53 h60
  text "35.43mil (0.900mm)" at 4668.7,1332.53 h60
  text "PTH" at 5290.45,1332.53 h60
  text "Round" at 5534.77,1332.53 h60
  text "A" at 4044.14,1322.54 h44.28
  text "29" at 4351.52,1232.91 h60
  text "40.00mil (1.016mm)" at 4668.7,1232.91 h60
  text "PTH" at 5290.45,1232.91 h60
  text "Round" at 5534.77,1232.91 h60
  text "4" at 4351.52,1133.29 h60
  text "51.18mil (1.300mm)" at 4668.7,1133.29 h60
  text "PTH" at 5290.45,1133.29 h60
  text "Round" at 5534.77,1133.29 h60
  text "3" at 4351.52,1033.66 h60
  text "52.00mil (1.321mm)" at 4668.7,1033.66 h60
  text "PTH" at 5290.45,1033.66 h60
  text "Round" at 5534.77,1033.66 h60
  text "8" at 4351.52,934.04 h60
  text "63.00mil (1.600mm)" at 4668.7,934.04 h60
  text "PTH" at 5290.45,934.04 h60
  text "Round" at 5534.77,934.04 h60
  text "4" at 4351.52,834.42 h60
  text "125.98mil (3.200mm)" at 4668.7,834.42 h60
  text "PTH" at 5290.45,834.42 h60
  text "Round" at 5534.77,834.42 h60
  text "533 Total" at 4351.52,734.8 h60
  text ".Layer_Name" at 577,-858.49 h60

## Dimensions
0,0 to 3500,0 on M2 Board Dimensions
0,0 to 0,2200 on M2 Board Dimensions
0,-400 to 1000,-400 on M2 Board Dimensions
